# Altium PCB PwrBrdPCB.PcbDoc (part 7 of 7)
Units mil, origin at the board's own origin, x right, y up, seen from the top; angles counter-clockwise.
Board outline 8000 x 5500 mil, 4 copper layers (Top Layer, Internal 1, Internal 2, Bottom Layer), stack 61.834 mil thick; 682 components, 380 nets, 1899 pads, 766 vias.
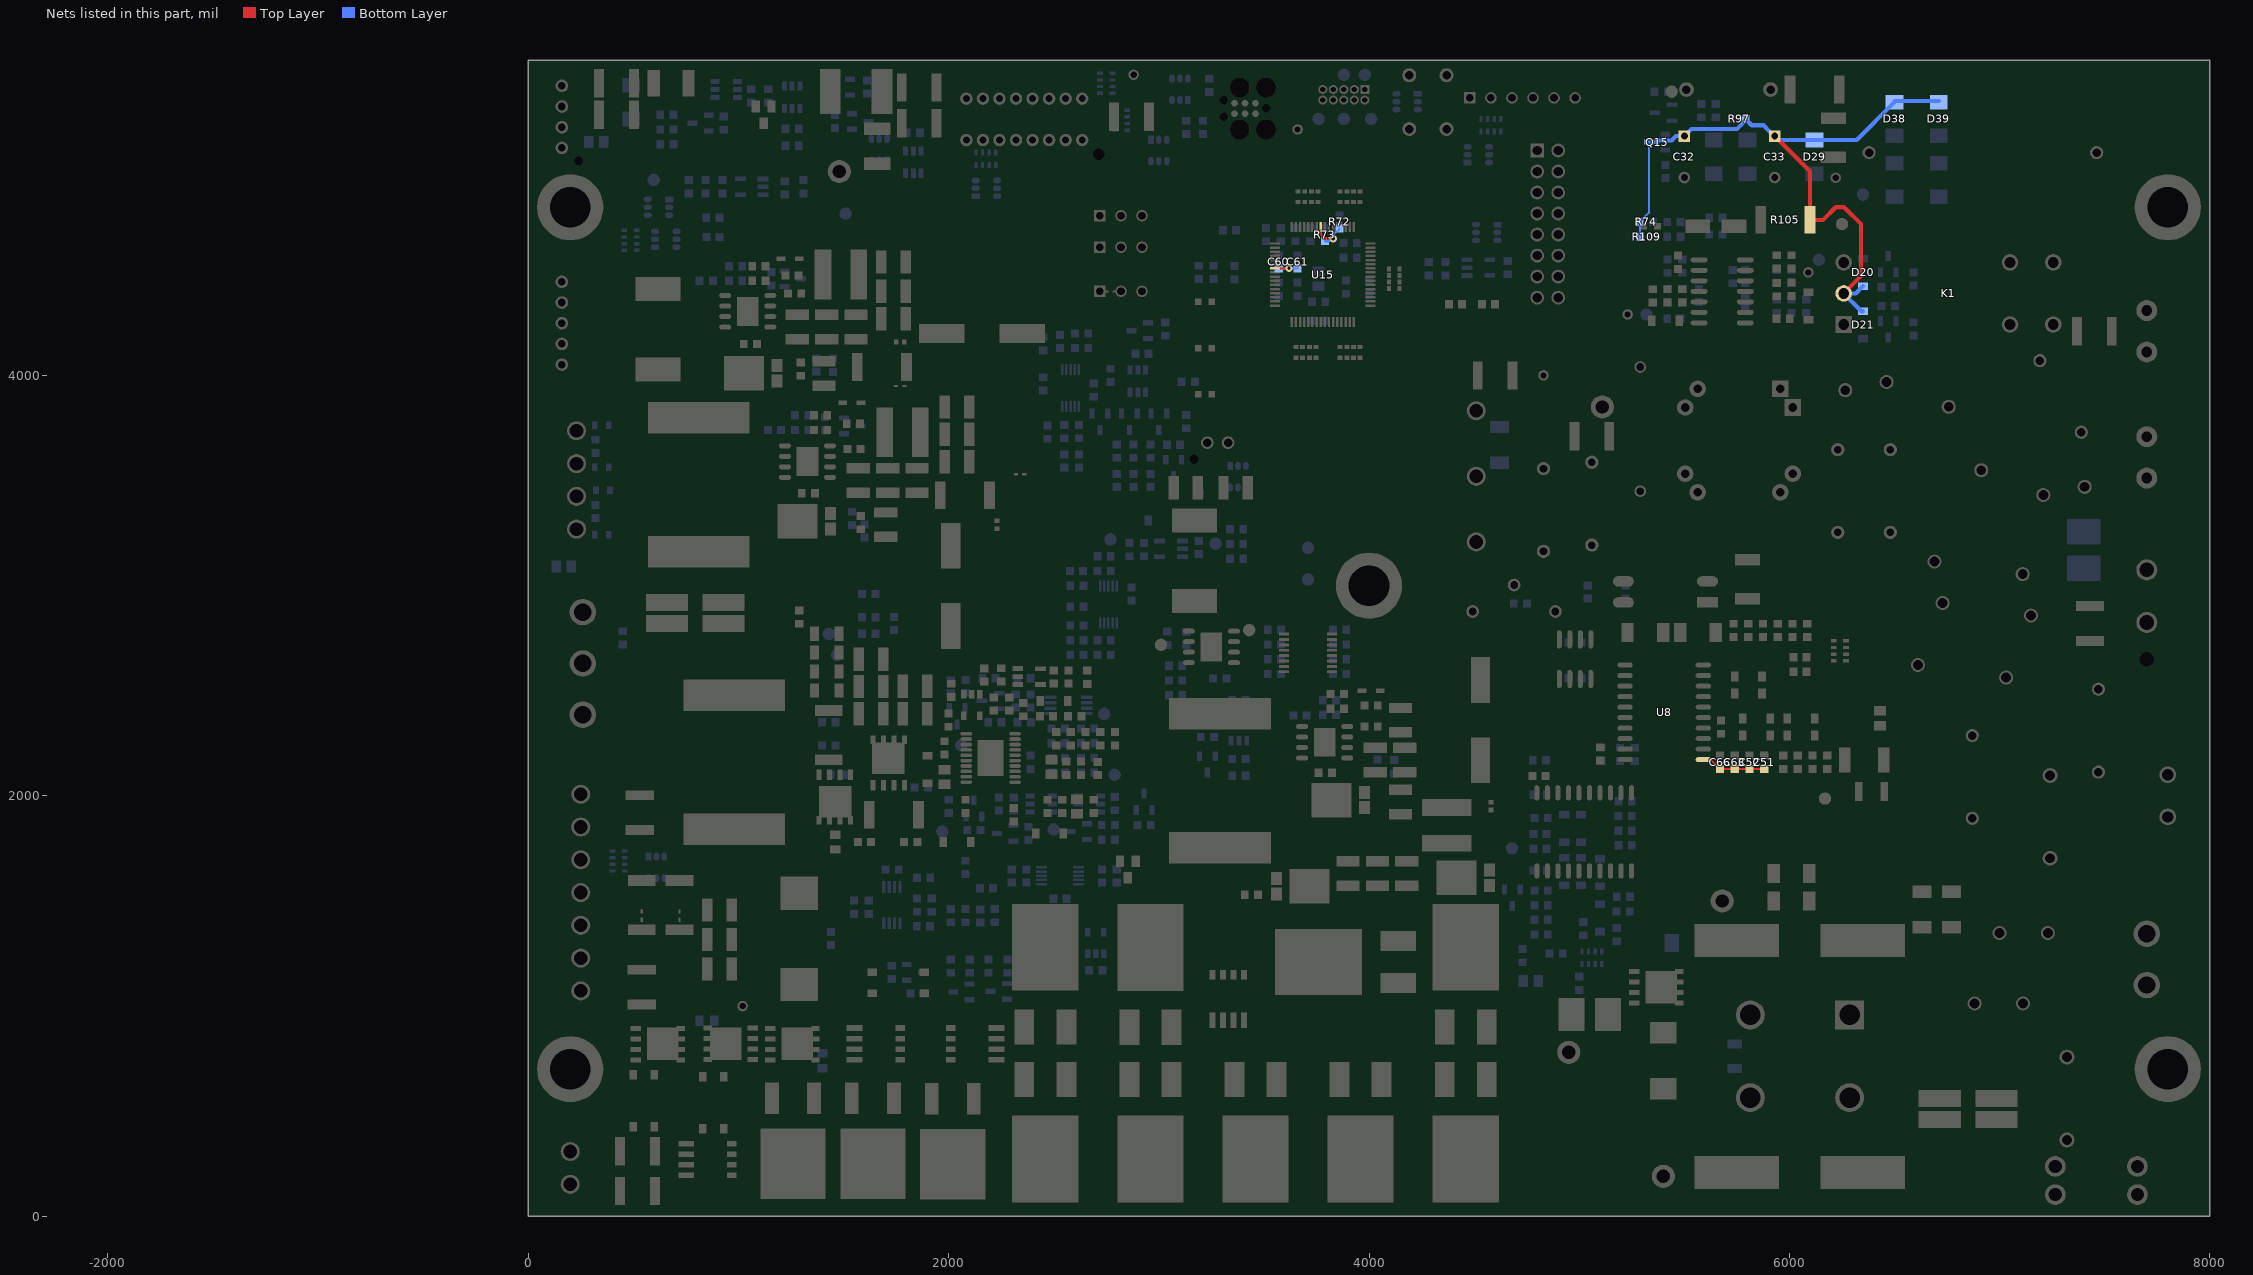
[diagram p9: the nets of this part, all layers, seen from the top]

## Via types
v1: diameter 35, hole 16, Top Layer to Bottom Layer, tented both sides, 409 vias
v2: diameter 35, hole 16, Top Layer to Bottom Layer, 348 vias
v3: diameter 35, hole 16, Top Layer to Bottom Layer, tented bottom, 5 vias
v4: diameter 60, hole 36, Top Layer to Bottom Layer, 2 vias
v5: diameter 65, hole 40.5, Top Layer to Bottom Layer, 2 vias

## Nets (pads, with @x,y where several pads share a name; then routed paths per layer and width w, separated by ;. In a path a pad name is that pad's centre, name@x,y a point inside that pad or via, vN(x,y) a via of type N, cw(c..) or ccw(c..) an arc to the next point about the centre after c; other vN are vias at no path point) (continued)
Vcoil: C32.+ C33.+ D20.K D21.K D29.K D38.K D39.K K1.PLUS Q15.3 R74.2 R97.2 R105.1 R109.2 | length 3385.7
  Top Layer w20: C33.+@5930,5138.43 6097.13,4971.3 R105.1@6097.13,4740 6160,4740 6220,4800 6260,4800 6340,4720 6340,4472.29 K1.PLUS@6257.71,4390
  Bottom Layer w10: R109.2@5288.5,4660 5288.5,4728.5 R74.2@5287.01,4730 5331,4773.99 Q15.3@5331,5110
  Bottom Layer w20: Q15.3@5331,5110 5370,5110 5377.9,5117.9 5439.66,5117.9 5460.19,5138.43 C32.+@5500,5138.43 5533.57,5172 5750.46,5172 5791.5,5213.04 R97.2@5791.5,5219.02 ; R97.2@5791.5,5220 R97.2@5791.5,5219.02 ; D21.K@6350,4305.35 6342.36,4305.35 K1.PLUS@6257.71,4390 6315.36,4390 D20.K@6350,4424.65 ; D39.K@6710,5305 6500,5305 D38.K@6500,5300 6320,5120 D29.K@6120,5120 5948.43,5120 C33.+@5930,5138.43 5928.23,5138.43 5928.23,5140.2 5912.44,5155.98 5910.67,5155.98 5876.65,5190 5820.51,5190 R97.2@5791.5,5219.02
VCORE: C60.1 C61.1 U15.55 | length 156.8
  Top Layer w10: U15.55@3553.62,4509.53 v1(3619.53,4509.53)
  Bottom Layer w10: C60.1@3570,4508.5 3571.02,4509.53 v1(3619.53,4509.53) 3658.98,4509.53 C61.1@3660,4508.5
VDDMON: C51.1 C52.1 C63.1 C66.1 U8.1 | length 308
  Top Layer w10: U8.1@5590.12,2172.24 5626.26,2172.24 C66.1@5670,2128.5 C63.1@5740,2128.5 C52.1@5810,2128.5 C51.1@5880,2128.5
WAKE_INT: R72.1 R73.2 U15.41 | length 210.3
  Top Layer w10: U15.41@3770.16,4706.38 3770.16,4669.84 3790,4650 v1(3830,4650)
  Bottom Layer w10: R73.2@3790,4638.5 3808.5,4638.5 3820,4650 v1(3830,4650) 3830,4668.5 R72.1@3860,4698.5
pads on no net: D10.3 D30.4 JP4.0 JP7.0 JP7.2 JP9. JP10.0 JP10.6 JP11.6 JP11.7 JP11.8 JP12.2 JP12.3 JP12.6 JP14.3 JY1.1 JY2.1 JY5.0 LA4.4 LA4.5 LA5.1 LA5.8 LA6.4 LA6.5 LA7.4 LA7.5 U3.1 U3.4 U4.14 U6.3 U8.12 U8.14 U13.2 U14.2 U18.4 U26.2 U29.3 Z1.1 Z5.1 Z6.1 Z9.1
copper on no net: | length 9736
  Top Layer w8: -2122,4675 -1000,4675 -1000,4770 -2122,4770 -2122,4675
  Internal 1 w8: -2122,4556 -1000,4556 -1000,4651 -2122,4651 -2122,4556
  Internal 2 w8: -2122,4439 -1000,4439 -1000,4534 -2122,4534 -2122,4439
  Bottom Layer w8: -2122,4321 -1000,4321 -1000,4416 -2122,4416 -2122,4321

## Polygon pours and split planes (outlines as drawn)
GND_AUX2 on Top Layer "aux2gnd-top" (solid, remove dead copper, pour order 72): 240,4520 870,4520 900,4550 1290,4550 1350,4610 1840,4610 1880,4570 1880,4350 2300,4350 2430,4220 2430,3950 2030,3950 2030,4030 1600,4030 1600,3900 240,3900
GND_ISO on Top Layer "gndisolarge-top" (solid, remove dead copper, pour order 76): 500,4530 500,5460 1870,5460 1870,5020 1890,5000 2780,5000 2880,5100 2880,5460 5040,5460 5040,4320 4210,4320 4210,3400 4510,3100 5280,3100 5310,3070 5310,1530 4520,1530 3350,2700 3350,3350 3310,3390 2460,3390 2460,4230 2310,4380 1910,4380 1910,4560 1830,4640 1330,4640 1270,4580 880,4580 830,4530
DCBUS on Top Layer "dcbus-top" (solid, remove dead copper, pour order 30): 715,291.81 650,340 650,370.55 650,1210 950,1510 1170,1510 1170,1430 1424.09,1430 1605.45,1620 2210,1620 2210,980 1070,980 1010,920 1010,400 880,400 880,291.81
GND_AUX1 on Top Layer "aux1gnd-top" (solid, remove dead copper, pour order 70): 360,3880 2150,3880 2150,3480 1990,3447.33 1990,3412 2150,3380 2150,2670 1900,2670 1820,2750 1820,3070 360,3070
PVPROT on Top Layer "pvprot-top" (solid, remove dead copper, pour order 8): 5990,30 5990,690 4660,690 4660,1458.06 3340,1450 3340,1630 2230,1630 2230,680 1110,680 1110,25
12V_ISO on Top Layer "12-top" (solid, remove dead copper, pour order 74): 3600,1680 2790,1680 2790,2300 2170,2920 2170,3220 2980,3220 2980,2280 3110,2150 3350,2150 3600,1900
GND_ISO on Top Layer "gndisosmall-top" (solid, remove dead copper, pour order 28): 4690,720 5020,720 5020,1050 4690,1050
N2 on Top Layer "n2-top" (solid, remove dead copper, pour order 40): 5050,3840 5050,3400 5640,3400 5630,3410 5630,3700 5310,3700 5170,3840
L2 on Top Layer "l2-top" (solid, remove dead copper, pour order 38): 5630,3800 5630,4070 4660,4070 4660,3930 5230,3930 5360,3800
LPROT on Top Layer "lprot-top" (solid, remove dead copper, pour order 36): 5840,3810 6100,3810 6140,3900 6140,4030 6300,4060 6520,4060 6590,3990 6590,3770 6730,3770 7090,4130 7090,4580 7010,4580 7000,4570 7000,4350 6800,4150 5950,4150 5840,4040
NetFC1_2 on Top Layer "pv-fused" (solid, pour order 0): 7430,30 7430,500 6890,500 6890,30
POS1 on Top Layer "pv-pos1" (solid, pour order 2): 6810,25 6810,490 6550,490 6350,690 6100,690 6100,25
PVNEG on Top Layer "pvneg-top" (solid, pour order 4): 6890,520 6890,1480 7830,1480 7830,1260 7620,1260 7170,810 7180,800 7180,520
NEG1 on Top Layer "pvneg1-top" (solid, pour order 6): 6810,520 6810,1250 6740,1250 6670,1320 6670,1400 6100,1400 6100,830 6310,830 6620,520
NEG2 on Top Layer "pvneg2-top" (solid, pour order 10): 5990,830 5990,1530 5950,1570 5460,1570 5390,1500 5390,920 5340,830
DCMON.N3 on Top Layer "dcmonn3-top" (solid, pour order 12): 5110,1360 5280,1360 5290,1350 5290,880 5110,880
HVX_SW on Top Layer "hvxsw-top" (solid, pour order 14): 740,1800 1650,1800 1650,1980 1670,2000 1740,2000 1750,2010 1750,2080 1590,2080 1550,2040 740,2040
GND_AUX3 on Internal 1 "gndaux3-gnds" (solid, remove dead copper, pour order 16): 2690,1770 2750,1830 2750,2310 2470,2590 1910,2590 1760,2740 1760,3030 890,3030 890,2650 850,2610 730,2610 730,1470 1420,1470 1710,1770
GND_ISO on Internal 1 "gndiso-gnds" (solid, remove dead copper, pour order 44): 4690,720 5310,720 5310,3070 5280,3100 4510,3100 4210,3400 4210,4320 4960,4320 5040,4400 5040,4980 5040,5040 5040,5500 -10,5500 -10,4750 500,4750 500,4540 510,4530 830,4530 880,4580 1270,4580 1330,4640 1830,4640 1910,4560 1910,4380 2310,4380 2500,4190 2500,4140 2460,4100 2460,3050 3110,2390 3110,1720 2860,1480 1860,1480 1410,1010 2800,1000 2950,1150 3230,1450 4690,1450
GND_ISO on Internal 1 "gndiso_trace" (solid, remove dead copper, pour order 66): 440,1010 1350,1010 1850,1510 2290,1510 2290,1520 2340,1570 2440,1570 2500,1510 2850,1510 2940,1600 2940,1620 2960,1640 2990,1640 3090,1740 3090,2380 2440,3030 2440,4120 2410,4150 1830,4150 1800,4120 1800,3930 1830,3900 2150,3900 2170,3880 2170,2660 2220,2610 2490,2610 2770,2330 2770,1780 2740,1750 1730,1750 1420,1440 440,1440
GND_AUX1 on Internal 1 "gndaux1-gnds" (solid, remove dead copper, pour order 20): 360,3070 1820,3070 1820,2750 1900,2670 2150,2670 2150,3870 2140,3880 360,3880
GND_MON on Internal 1 "gndmon-gnds" (solid, remove dead copper, pour order 48): 5540,1940 5540,2860 6300,2860 6300,1940
GND_PROT on Internal 1 "gndprot-gnds" (solid, remove dead copper, pour order 60): 5320,5390 5320,4240 6640,4240 6640,5390
GND_AUX2 on Internal 1 "gndaux2-gnds" (solid, remove dead copper, pour order 22): 400,3940 1710,3940 1710,4160 1720,4170 2460,4170 2460,4190 2300,4350 1880,4350 1880,4570 1840,4610 1350,4610 1290,4550 900,4550 830,4480 400,4480
3V3_ISO on Internal 2 "3v3iso-pwrs" (solid, remove dead copper, pour order 46): 5310,1450 5310,3070 5280,3100 4510,3100 4210,3400 4210,4320 4960,4320 5040,4400 5040,4980 5040,5100 5040,5500 0,5500 0,4750 500,4750 500,4530 830,4530 880,4580 1270,4580 1330,4640 1830,4640 1910,4560 1910,4380 2310,4380 2500,4190 2500,4140 2430,4070 2430,3070 3110,2390 3110,1720 2870,1490 1860,1480 1720,1330 1723.94,1003.94 2240,1003.94 2240,1450 3090,1450
DCBUS on Internal 2 "dcbus_trace" (solid, remove dead copper, pour order 68): 1040,760 1040,950 1070,980 1630,980 1690,1040 1690,1350 1850,1510 2280,1510 2340,1570 2440,1570 2500,1510 2850,1510 3090,1750 3090,2380 2640,2830 2410,2830 2100,3140 2100,4040 1870,4270 1870,4550 1820,4600 1460,4600 1410,4550 1410,4040 1770,3680 1770,2750 1900,2620 2500,2620 2780,2340 2780,1810 2720,1750 1750,1750 1240,1240 750,1240 750,760
VCC_AUX3 on Internal 2 "vccaux3-pwrs" (solid, remove dead copper, pour order 18): 1880,1770 1880,2170 1990,2280 1990,2590 2470,2590 2750,2310 2750,1830 2690,1770
GND_ISO on Internal 2 "gndisoforcomp-pwrs" (solid, remove dead copper, pour order 26): 450,1210 720,1210 720,1800 710,2200 710,2540 850,2650 1390,2640 1390,2770 1730,2920 1730,3000 1730,3090 850,3090 780,3030 780,2780 570,2600 570,2240 450,2240 450,2110 450,1930
Vcc_prot on Internal 2 "vccprot-pwrs" (solid, remove dead copper, pour order 62): 5320,5390 5320,4240 6640,4240 6640,5390
GND_ISO on Bottom Layer "gndisoCPU-bot" (solid, remove dead copper, pour order 50): 4690,1030 5310,1030 5310,1940 6300,1940 6300,2860 5310,2860 5310,3070 5270,3110 4500,3110 4210,3400 4210,4320 4870,4980 5160,4980 5160,5500 0,5500 0,4750 500,4750 500,4530 820,4530 870,4580 1270,4580 1330,4640 1830,4640 1910,4560 1910,4380 2320,4380 2500,4200 2500,4140 2450,4090 2440,4090 2440,3020 3090,2370 3090,1453 3087,1450 4690,1450
GND_AUX2 on Bottom Layer "gndaux2-bot" (solid, remove dead copper, pour order 56): 400,3940 1700,3940 1730,3970 2420,3970 2420,4230 2300,4350 2100,4350 1840,4610 1350,4610 1290,4550 890,4550 840,4500 400,4500
NEG2 on Bottom Layer "neg2-bot" (solid, remove dead copper, pour order 58): 5350,830 5980,830 5990,840 5990,1210 5350,1210
GND_AUX3 on Bottom Layer "gndaux3-bot" (solid, remove dead copper, pour order 52): 1310,2770 1810,2770 1990,2590 2490,2590 2730,2350 2730,1810 2690,1770 1840,1770 1840,2090 1310,2090
GND_AUX1 on Bottom Layer "gndaux1-bot" (solid, remove dead copper, pour order 54): 460,3070 2150,3070 2160,3080 2160,3880 460,3880
GND_ISO on Bottom Layer "gndiso-bot" (solid, remove dead copper, pour order 24): 5020,1010 5020,40 580,50 580,340 420,500 420,1320 490,1390 750,1390 790,1350 790,1100 1000,890 2820,890 3240,1310 3500,1310 3800,1010
PVNEG on Bottom Layer "pvneg-bot" (solid, remove dead copper, pour order 64): 6890,530 7180,530 7180,820 7620,1260 7830,1260 7830,1480 6890,1480
GND on Bottom Layer "earth-bot" (solid, remove dead copper, pour order 42): 8000,2200 8010,2190 8010,1770 6680,1770 6560,1890 6560,2080 6680,2200
PROT.NPROT on Bottom Layer "nprot-bot" (solid, remove dead copper, pour order 34): 7480,3310 7410,3310 7240,3480 6820,3480 6700,3600 6420,3600 6290,3730 6220,3660 5930,3660 5840,3570 5840,3380 5870,3350 6590,3350 6780,3160 6850,3160 7010,3320 7270,3320
HVX_DCBUS on Bottom Layer "hvxdcbus-bot" (solid, remove dead copper, pour order 32): 1600,1570 1770,1740 1810,1740 1810,2070 1190,2070 1190,1570

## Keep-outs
Keep-Out Layer:
  circle w10: c7800,4800 r170
  circle w10: c200,4800 r170
  circle w10: c200,700 r170
  circle w10: c4000,3000 r170
  lines w10: 25,4170 25,4420 ; 25,25 1512.5,25 3025,25 7975,25 7975,5475 25,5475 25,25

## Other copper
Top Layer:
  rectangle net NetF5_2: 502.87,5330.74 597.32,5449.84
  rectangle net FAN_DRAIN: 762.68,5330.74 868.31,5449.84
  rectangle net NetD57_1: 1154.32,5279.37 1436.97,5449.84
  rectangle net NetD57_1: 1157.4,5279.37 1436.97,5284.98
  rectangle net GND_ISO: 2210,3360 2390,3500
  rectangle net NetQ32_S: 1420,2080 1550,2210
  rectangle: -2122,4675 -1932,4770
  region net HVX_DCBUS: 1200,1460 1200,1730 1310,1730 1340,1760 1520,1760 1520,1560 1420,1460
  region net GND_AUX3: 1150,1550 1150,1730 744.7,1730 744.7,1550 870,1490 930,1550
  pour cut-out: 1920,5500 1920,5000 2760,5000 2760,5500
  region net HVX_DCBUS: 1640,2110 1640,2310 1670,2340 1670,2700 1730,2700 1820,2610 1820,2140 1790,2110
  region net GND_AUX3: 1440,2340 1440,2810 1370,2870 1070,2870 1050,2880 830,2880 830,3040 1750,3040 1750,2740 1620,2740 1620,2340
  region net NetC153_1: 150,2280 590,2280 660,2350 660,2610 740,2690 750,2730 760,2780 760,2860 550,2860 420,2730 420,2610 330,2520 150,2520
  region net NetC153_2: 760,2880 520,2880 370,2730 150,2730 150,3040 710,3040 760,2960
  region net NetC90_2: 1320,3230 1320,3460 1290,3460 1240,3510 1240,3520 1190,3520 1050,3650 1050,3760 610,3760 1160,3230
  region net 12V_AUX1: 370,3090 1630,3090 1750,3210 1750,3260 1630,3260 1610,3280 1550,3280 1550,3250 1490,3190 370,3190
  region net DCBUS: 1900,3610 1950,3560 2010,3560 2010,3900 1830,3900 1830,3840
  region net DCBUS: 1650,4300 1600,4350 1600,4600 1700,4600 1700,4300
  region net GND_AUX2: 1160,4150 1210,4200 1600,4200 1600,4060 1590,4050 1220,4050 1210,4040 1210,3990 1160,3990
  region net NetC98_2: 1040,3980 1040,4170 1010,4170 940,4240 890,4240 719.05,4410.95 509.06,4410.94 940,3980
  region net NetC17_2: 3780,2120 3740,2120 3690,2170 3690,2190 3640,2190 3510,2320 3280,2320 3690,1900 3780,1900
  region net GND_ISO: 3950,1920 4000,1920 4000,1960 4040,2000 4200,2000 4200,2140 3950,2140
  region net NetC24_1: 4030,2210 4200,2210 4270,2150 4270,1980 4450,1980 4450,2210 4340,2320 4100,2320 4110,2310 4110,2250 4030,2250
  region net HVX_VOUT: 1270,2400 1340,2470 1390,2470 1390,2800 1360,2830 830,2830 830,2680 740,2590 740,2400
  region net PV_SEL-: 1040,870 1100,870 1110,880 1130,900 1180,900 1180,770 1120,770 1110,760 1090,740 1040,740
  text "TOP LAYER *.GTL" at -1862,4702 h40
Internal 1:
  rectangle: -2122,4557 -1932,4652
  pour cut-out: 1920,5460 1920,5020 2760,5020 2760,5460
  text "INTERNAL LAYER 1 *.G1" at -1862,4584 h40
Internal 2:
  rectangle: -2122,4439 -1932,4534
  pour cut-out: 1910,5470 1910,5040 2760,5040 2760,5470
  text "INTERNAL LAYER 2 *.G2" at -1862,4466 h40
Bottom Layer:
  rectangle net NetFC1_2: 6890,40 7430,490
  rectangle net PVPROT: 5060,40 5990,690
  rectangle net NetL9_1: 3200,2650 3300,2770
  rectangle net PVPROT: 2380,1080 2590,1410
  rectangle net DCBUS: 880,760 1000,880
  rectangle net PVPROT: 1070,760 1760,910
  rectangle: -2122,4321 -1932,4416
  region net GND_AUX1: 1820,2990 1820,2790 1920,2690 2380,2690 2420,2730 2420,2990
  region net NEG1: 6100,830 6310,830 6610,530 6700,530 6700,1290 6590,1400 6100,1400
  region net POS1: 6100,40 6100,690 6350,690 6550,490 6810,490 6810,40
  region net DCBUS: 870,1160 870,936 870,760 1050,760 1050,970 1660,970 1660,1160
  region net GND_AUX3: 730,1730 730,1570 950,1350 1150,1350 1150,1730
  region net PVPROT: 3830,1040 3510,1360 3510,1420 4640,1420 4640,1040
  region net PVPROT: 2820,1460 3040,1460 3040,1340 2820,1120
  region net HVX_VOUT: 890,2950 890,2700 730,2540 730,1770 1150,1770 1150,2110 1280,2110 1280,2410 1280,2980 920,2980
  pour cut-out: 1920,5000 2760,5000 2760,5500 1920,5500
  text "BOTTOM LAYER *.GBL" at -1862,4348 h40

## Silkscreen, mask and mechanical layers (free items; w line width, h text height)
Top Overlay:
  drawing of 178 lines, arcs and shapes, not listed
  text "FTDI cable" at 4530,5400 h50
  text "Fan+" at 840,5390 h60
  text "BLK" at 4450,5250 h60 r270
  text "BRN" at 4550,5250 h60 r270
  text "RED" at 4650,5250 h60 r270
  text "OR" at 4750,5250 h60 r270
  text "YEL" at 4850,5250 h60 r270
  text "GRN" at 4950,5250 h60 r270
  text "Fan-" at 580,5231.89 h60
  text "reset" at 4140,5080 h60
  text "1" at 2760,5050 h60
  text "5V" at 5060,5050 h60
  text "FG" at 370,5020 h60
  text "GND" at 4470,5010 h60
  text "TP15" at 2002.58,4990 h40 r270
  text "Comp" at 2082.58,4990 h40 r270
  text "FG" at 2162.58,4990 h40 r270
  text "Fan" at 2242.58,4990 h40 r270
  text "12V" at 2322.58,4990 h40 r270
  text "GND" at 2402.58,4990 h40 r270
  text "PComp" at 2482.58,4990 h40 r270
  text "AC OK" at 2562.58,4990 h40 r270
  text "1" at 330,4970 h50
  text "12V" at 4980,4960 h60
  text "TOP OVERLAY *.GTO" at -1862,4938 h40
  text "3V3" at 4470,4930 h60
  text "AC over / voltage" at 5050,4910 h60 r270
  text "GND ISO" at 1030,4860 h60
  text "SDA" at 4470,4830 h60
  text "normal / prog" at 3020,4810 h60
  text "PWR_WAKE" at 2002.58,4770 h40 r270
  text "SEL/test" at 2082.58,4770 h40 r270
  text "nRST" at 2162.58,4770 h40 r270
  text "Bat+" at 2242.58,4770 h40 r270
  text "5V" at 2322.58,4770 h40 r270
  text "PWR2DAQ" at 2402.58,4770 h40 r270
  text "DAQ2PWR" at 2482.58,4770 h40 r270
  text "GND" at 2562.58,4770 h40 r270
  text "SCL" at 4470,4740 h60
  text "LED0" at 4480,4640 h60
  text "LED1" at 4480,4540 h60
  text "CTL_COMP" at 4270,4450 h60
  text "spare" at 4290,4380 h60
  text "LED1" at 3310,4330 h60
  text "PWR | CTL" at 2610,4250 h50
  text "RED" at 3310,4250 h60
  text "2A fuse" at 7830,4130 h60 r270
  text "LED0" at 3310,4120 h60
  text "COMP.EN / source" at 2650,4100 h50
  text "YEL" at 3310,4050 h60
  text "1" at 310,3950 h60
  text "power" at 3310,3890 h60
  text "Revision" at 3640,3880 h60
  text "GND" at 3090,3780 h60
  text "5V" at 3300,3780 h60
  text ".nhRev" at 3685,3680 h120
  text "+5" at 25,3630 h60 r270
  text "NH-GG MF / Solar Power / Board" at 2370,3610 h60
  text "Serial #" at 3630,3550 h60
  text "c 2020-03" at 2400,3500 h60
  text "+12" at 30,3340 h60 r270
  text "Licensed under" at 2288.8,3190 h50
  text "1" at 290,3130 h60
  text "CERN-OHL-P v2" at 2288.8,3120 h50
  text "Source package at" at 2288.8,3050 h50
  text "AC / Line" at 7310,3030 h60
  text "Neg" at 40,3020 h60 r270
  text "docs.2to8.cc" at 2288.8,2980 h50
  text "5V" at 3470,2860 h60
  text "12V" at 2820,2750 h60
  text "CR2032" at 4540,2710 h50
  text "AC / Neut" at 7330,2540 h60
  text "Pos" at 50,2400 h60 r270
  text "1" at 510,2310 h60
  text "EARTH" at 7624.72,2124.72 h60 r270
  text "-" at 60,1970 h60
  text "C" at 60,1820 h60
  text "+" at 60,1670 h60
  text "D" at 60,1510 h60
  text "PV-" at 7340,1410 h60 r270
  text "trt" at 40,1350 h60
  text "T" at 60,1200 h60
  text "PV+" at 7340,1150 h60 r270
  text "ts" at 40,1070 h60
  text "1" at 80,960 h60
  text "PV-" at 5030,730 h60
  text "EARTH" at 7655.28,434.72 h60
  text "Pos" at 50,390 h60
  text "PV+" at 5350,280 h60
  text "20A fuse" at 6670,180 h60
  text "1" at 80,140 h60
  text "Neg" at 40,50 h60
Bottom Overlay:
  drawing of 151 lines, arcs and shapes, not listed
  text "BOTTOM OVERLAY *.GBO" at -1862,3994 h40
  text "Licensed under" at 3871.35,878.04 h50
  text "CERN-OHL-P v2" at 3871.35,799.3 h50
  text "Source package at" at 3871.35,720.56 h50
  text "https://docs.2to8.cc" at 3871.35,641.82 h50
Top Paste:
  rectangle: -2122,5029 -1932,5124
  lines w8: -2122,5029 -2122,5124 -1000,5124 -1000,5029 -2122,5029
  text "TOP PASTE *.GTP" at -1862,5056 h40
Bottom Paste:
  rectangle: -2122,4085 -1932,4180
  lines w8: -2122,4085 -1000,4085 -1000,4180 -2122,4180 -2122,4085
  text "BOTTOM PASTE *.GBP" at -1862,4112 h40
Top Solder:
  rectangle: -2122,4793 -1932,4888
  lines w8: -2122,4793 -1000,4793 -1000,4888 -2122,4888 -2122,4793
  text "TOP SOLDER MASK *.GTS" at -1862,4820 h40
Bottom Solder:
  rectangle: 850,310 4930,560
  rectangle: 3740,2190 3840,2320
  rectangle: 3200,2650 3290,2770
  rectangle: 2140,2100 2260,2260
  rectangle: 1280,3520 1380,3660
  rectangle: 1000,4240 1090,4370
  rectangle: 1070,2670 1230,2810
  rectangle: 1640,2110 1780,2250
  rectangle: 5360,1020 5450,1160
  rectangle: 890,770 990,870
  rectangle: 1230,770 1330,870
  rectangle: -2122,4203 -1932,4298
  lines w8: -2122,4203 -1000,4203 -1000,4298 -2122,4298 -2122,4203
  lines w30: 810,220 860,220 ; 810,320 860,320 ; 1170,120 4610,120
  text "BOTTOM SOLDER MASK *.GBS" at -1862,4230 h40
1 Fab Drawing:
  circle w10: c200,4800 r75
  circle w10: c200,700 r75
  circle w10: c7800,700 r75
  circle w10: c7800,4800 r75
  circle w10: c4000,3000 r75
  lines w5: -6580,-3400 9120,-3400 9120,7600 -6580,7600 -6580,-3400
  lines w10: 4618.38,-3031.5 8868.38,-3031.5 ; 4618.38,-2531.5 8868.38,-2531.5 ; 4618.38,-2031.5 8868.38,-2031.5
  text "NEW HORIZONS, GHL" at 4723.38,-2401.5 h250
  text "PROJECT" at 4711.1,-2631.5 h60
  text "REV" at 7416.02,-2631.5 h60
  text "'.nhRev'" at 7386.02,-2906.5 h280
  text "'.nhProjName'" at 4740.98,-2915.2 h260
  text "FABRICATION DRAWING" at 6193.38,-3186.5 h100
2 Board Outline:
  rectangle: -2122,3849 -1932,3944
  lines w8: -2122,3849 -2122,3944 -1000,3944 -1000,3849 -2122,3849
  lines w10: 0,0 2500,0 3000,0 8000,0 8000,5500 0,5500 0,0
  lines w93: 7600,2950 7800,2950
  text "BOARD OUTLINE *.GM2" at -1862,3876 h40
4 Gerber All:
  lines w8: -2222,3767.67 -2222,5434 -900,5434 -900,3767.67 -2222,3767.67
  lines w10: -1932,5214 -1162,5214
  text "LAYER USAGE" at -1932,5242 h80
5 Assembly Top:
  lines w5: -6580,-3400 -6580,7600 9120,7600 9120,-3400 -6580,-3400
  lines w10: 4618.38,-3031.5 8868.38,-3031.5 ; 4618.38,-2531.5 8868.38,-2531.5 ; 4618.38,-2031.5 8868.38,-2031.5
  text "NEW HORIZONS, GHL" at 4723.38,-2401.5 h250
  text "PROJECT" at 4711.1,-2631.5 h60
  text "REV" at 7416.02,-2631.5 h60
  text "PRIMARY SIDE" at -727.76,-2706.54 h300
  text "'.nhRev'" at 7386.02,-2906.5 h280
  text "'.nhProjName'" at 4740.98,-2915.2 h260
  text "ASSEMBLY DRAWING, TOP" at 6193.38,-3186.5 h100
6 Assembly Bot:
  lines w5: -6580,-3400 -6580,7600 9120,7600 9120,-3400 -6580,-3400
  lines w10: -6428.39,-3031.5 -2178.39,-3031.5 ; -6428.39,-2531.5 -2178.39,-2531.5 ; -6428.39,-2031.5 -2178.39,-2031.5
  text "NEW HORIZONS, GHL" at -2283.39,-2401.5 h250
  text "REV" at -4976.03,-2631.5 h60
  text "Project" at -2271.11,-2631.5 h60
  text "SECONDARY SIDE" at 3082.24,-2701.54 h300
  text "'.nhRev'" at -4946.03,-2906.5 h280
  text "'.nhProjName'" at -2300.99,-2915.2 h260
  text "ASSEMBLY DRAWING, BOTTOM" at -3753.39,-3186.5 h100
7 Fab Notes:
  drawing of 304 lines, arcs and shapes, not listed
  text "MATERIAL:  FR4" at -6067.8,7357.29 h100
  text "4 LAYERS OF 1OZ COPPER" at -6067.8,7257.29 h100
  text "SILVER IMMERSION" at -6067.8,7157.29 h100
  text "FINISHED BOARD THICKNESS = 0.062\" / 1.57mm" at -6067.8,6957.29 h100
  text "UL 94V-0" at -6067.8,6857.29 h100
  text "GREEN SOLDERMASK OVER BARE COPPER, BOTH SIDES" at -6067.8,6657.29 h100
  text "WHITE SILKSCREEN OVER SOLDERMASK" at -6067.8,6557.29 h100
  text "DIMENSIONS IN MILS (0.001\")" at -6067.8,6357.29 h100
  text "dia 0.200in (5mm) x5" at 400,5700 h60
  text "Layer" at -5922.5,1957.5 h60
  text "Name" at -5512.59,1957.5 h60
  text "Material" at -4582.84,1957.5 h60
  text "Thickness" at -3723.08,1957.5 h60
  text "Constant" at -3073.24,1957.5 h60
  text "Board Layer Stack" at -2503.38,1957.5 h60
  text "Top Overlay" at -5512.59,1837.5 h60
  text "Top Solder" at -5512.59,1717.5 h60
  text "Solder Resist" at -4582.84,1717.5 h60
  text "0.40mil" at -3723.08,1717.5 h60
  text "3.5" at -3073.24,1717.5 h60
  text "1" at -5922.5,1597.5 h60
  text "Top Layer" at -5512.59,1597.5 h60
  text "1.40mil" at -3723.08,1597.5 h60
  text "Dielectric 1" at -5512.59,1477.5 h60
  text "FR-4" at -4582.84,1477.5 h60
  text "14.10mil" at -3723.08,1477.5 h60
  text "4.2" at -3073.24,1477.5 h60
  text "2" at -5922.5,1357.5 h60
  text "Internal 1" at -5512.59,1357.5 h60
  text "1.42mil" at -3723.08,1357.5 h60
  text "Dielectric 3" at -5512.59,1237.5 h60
  text "FR-4" at -4582.84,1237.5 h60
  text "28.00mil" at -3723.08,1237.5 h60
  text "4.2" at -3073.24,1237.5 h60
  text "3" at -5922.5,1117.5 h60
  text "Internal 2" at -5512.59,1117.5 h60
  text "1.42mil" at -3723.08,1117.5 h60
  text "Dielectric 2" at -5512.59,997.5 h60
  text "FR-4" at -4582.84,997.5 h60
  text "14.10mil" at -3723.08,997.5 h60
  text "4.2" at -3073.24,997.5 h60
  text "4" at -5922.5,877.5 h60
  text "Bottom Layer" at -5512.59,877.5 h60
  text "1.40mil" at -3723.08,877.5 h60
  text "Bottom Solder" at -5512.59,757.5 h60
  text "Solder Resist" at -4582.84,757.5 h60
  text "0.40mil" at -3723.08,757.5 h60
  text "3.5" at -3073.24,757.5 h60
  text "Bottom Overlay" at -5512.59,637.5 h60
  text "NEW HORIZONS, GHL" at 4723.38,-2401.5 h250
  text "PROJECT" at 4711.1,-2631.5 h60
  text "REV" at 7416.02,-2631.5 h60
  text "'.nhEngName'" at 8105,-2650 h90
  text "'.nhEngPhone'" at 8105,-2750 h90
  text "'.nhEngEmail'" at 8105,-2850 h90
  text "'.nhRev'" at 7386.02,-2906.5 h280
  text "'.nhProjName'" at 4740.98,-2915.2 h260
  text "'.nhToday'" at 8105,-2950 h90
  text "FABRICATION NOTES" at 6191.77,-3186.5 h100
Drill Drawing:
  circle w10: c-5899.38,5035.83 r20
  circle w10: c-5899.38,5035.83 r33.33
  circle w10: c-5899.38,2785.83 r33.33
  lines w10: -5932.71,2619.17 -5916.04,2619.17 -5899.38,2602.5 -5882.71,2619.17 -5866.04,2619.17 -5882.71,2635.83 -5866.04,2652.5 -5882.71,2652.5 -5899.38,2669.17 -5916.04,2652.5 -5932.71,2652.5 -5916.04,2635.83 -5932.71,2619.17 ; -5932.71,2902.5 -5932.71,2919.17 -5916.04,2935.83 -5932.71,2952.5 -5932.71,2969.17 -5916.04,2969.17 -5899.38,2952.5 -5882.71,2969.17 -5866.04,2969.17 -5866.04,2952.5 -5882.71,2935.83 -5866.04,2919.17 -5866.04,2902.5 -5882.71,2902.5 -5899.38,2919.17 -5916.04,2902.5 -5932.71,2902.5 ; -5932.71,3202.5 -5866.04,3202.5 -5866.04,3269.17 -5932.71,3269.17 -5932.71,3202.5 ; -5932.71,3369.17 -5916.04,3369.17 -5899.38,3352.5 -5882.71,3369.17 -5866.04,3369.17 -5882.71,3385.83 -5866.04,3402.5 -5882.71,3402.5 -5899.38,3419.17 -5916.04,3402.5 -5932.71,3402.5 -5916.04,3385.83 -5932.71,3369.17 ; -5932.71,4252.5 -5932.71,4269.17 -5916.04,4285.83 -5932.71,4302.5 -5932.71,4319.17 -5916.04,4319.17 -5899.38,4302.5 -5882.71,4319.17 -5866.04,4319.17 -5866.04,4302.5 -5882.71,4285.83 -5866.04,4269.17 -5866.04,4252.5 -5882.71,4252.5 -5899.38,4269.17 -5916.04,4252.5 -5932.71,4252.5 ; -5932.71,4919.17 -5866.04,4919.17 -5899.38,4852.5 -5932.71,4919.17 ; -5919.38,2915.83 -5919.38,2925.83 -5909.38,2935.83 -5919.38,2945.83 -5919.38,2955.83 -5909.38,2955.83 -5899.38,2945.83 -5889.38,2955.83 -5879.38,2955.83 -5879.38,2945.83 -5889.38,2935.83 -5879.38,2925.83 -5879.38,2915.83 -5889.38,2915.83 -5899.38,2925.83 -5909.38,2915.83 -5919.38,2915.83 ; -5919.38,3215.83 -5879.38,3215.83 -5879.38,3255.83 -5919.38,3255.83 -5919.38,3215.83 ; -5919.38,3375.83 -5909.38,3375.83 -5899.38,3365.83 -5889.38,3375.83 -5879.38,3375.83 -5889.38,3385.83 -5879.38,3395.83 -5889.38,3395.83 -5899.38,3405.83 -5909.38,3395.83 -5919.38,3395.83 -5909.38,3385.83 -5919.38,3375.83
  lines w15: -5992.5,2557.5 -2407.44,2557.5 ; -5992.5,5407.5 -2407.44,5407.5 ; -5441.62,2407.5 -5441.62,5557.5 ; -4841.78,2407.5 -4841.78,5557.5 ; -3692.12,2407.5 -3692.12,5557.5 ; -3186.24,2407.5 -3186.24,5557.5 ; -5992.5,2407.5 -2407.44,2407.5 -2407.44,5557.5 -5992.5,5557.5 -5992.5,2407.5
  text "Symbol" at -5902.5,5452.5 h72
  text "Count" at -5396.62,5452.5 h72
  text "Hole Size" at -4796.78,5452.5 h72
  text "Plated" at -3647.12,5452.5 h72
  text "Hole Type" at -3141.24,5452.5 h72
  text "1" at -5396.62,5302.5 h60
  text "70.00mil (1.778mm)" at -4796.78,5302.5 h60
  text "NPTH" at -3647.12,5302.5 h60
  text "Round" at -3141.24,5302.5 h60
  text "H" at -5931.59,5292.51 h66.67
  text "2" at -5396.62,5152.5 h60
  text "70.00mil (1.778mm)" at -4796.78,5152.5 h60
  text "PTH" at -3647.12,5152.5 h60
  text "Round" at -3141.24,5152.5 h60
  text "I" at -5920.48,5142.51 h66.67
  text "3" at -5396.62,5002.5 h60
  text "40.50mil (1.029mm)" at -4796.78,5002.5 h60
  text "NPTH" at -3647.12,5002.5 h60
  text "Round" at -3141.24,5002.5 h60
  text "3" at -5396.62,4852.5 h60
  text "53.50mil (1.359mm)" at -4796.78,4852.5 h60
  text "PTH" at -3647.12,4852.5 h60
  text "Round" at -3141.24,4852.5 h60
  text "4" at -5396.62,4702.5 h60
  text "93.50mil (2.375mm)" at -4796.78,4702.5 h60
  text "NPTH" at -3647.12,4702.5 h60
  text "Round" at -3141.24,4702.5 h60
  text "V" at -5931.59,4692.51 h66.67
  text "4" at -5396.62,4552.5 h60
  text "98.43mil (2.500mm)" at -4796.78,4552.5 h60
  text "PTH" at -3647.12,4552.5 h60
  text "Round" at -3141.24,4552.5 h60
  text "M" at -5931.59,4542.51 h66.67
  text "5" at -5396.62,4402.5 h60
  text "82.68mil (2.100mm)" at -4796.78,4402.5 h60
  text "PTH" at -3647.12,4402.5 h60
  text "Round" at -3141.24,4402.5 h60
  text "E" at -5931.59,4392.51 h66.67
  text "5" at -5396.62,4252.5 h60
  text "193.00mil (4.902mm)" at -4796.78,4252.5 h60
  text "PTH" at -3647.12,4252.5 h60
  text "Round" at -3141.24,4252.5 h60
  text "7" at -5396.62,4102.5 h60
  text "30.00mil (0.762mm)" at -4796.78,4102.5 h60
  text "PTH" at -3647.12,4102.5 h60
  text "Round" at -3141.24,4102.5 h60
  text "D" at -5931.59,4092.51 h66.67
  text "9" at -5396.62,3952.5 h60
  text "63.00mil (1.600mm)" at -4796.78,3952.5 h60
  text "PTH" at -3647.12,3952.5 h60
  text "Round" at -3141.24,3952.5 h60
  text "J" at -5931.59,3942.51 h66.67
  text "10" at -5396.62,3802.5 h60
  text "25.00mil (0.635mm)" at -4796.78,3802.5 h60
  text "PTH" at -3647.12,3802.5 h60
  text "Round" at -3141.24,3802.5 h60
  text "O" at -5931.59,3792.51 h66.67
  text "11" at -5396.62,3652.5 h60
  text "51.18mil (1.300mm)" at -4796.78,3652.5 h60
  text "PTH" at -3647.12,3652.5 h60
  text "Round" at -3141.24,3652.5 h60
  text "G" at -5931.59,3642.51 h66.67
  text "16" at -5396.62,3502.5 h60
  text "64.96mil (1.650mm)" at -4796.78,3502.5 h60
  text "PTH" at -3647.12,3502.5 h60
  text "Round" at -3141.24,3502.5 h60
  text "C" at -5931.59,3492.51 h66.67
  text "18" at -5396.62,3352.5 h60
  text "43.70mil (1.110mm)" at -4796.78,3352.5 h60
  text "PTH" at -3647.12,3352.5 h60
  text "Round" at -3141.24,3352.5 h60
  text "20" at -5396.62,3202.5 h60
  text "33.00mil (0.838mm)" at -4796.78,3202.5 h60
  text "PTH" at -3647.12,3202.5 h60
  text "Round" at -3141.24,3202.5 h60
  text "20" at -5396.62,3052.5 h60
  text "47.24mil (1.200mm)" at -4796.78,3052.5 h60
  text "PTH" at -3647.12,3052.5 h60
  text "Round" at -3141.24,3052.5 h60
  text "A" at -5931.59,3042.51 h66.67
  text "26" at -5396.62,2902.5 h60
  text "40.50mil (1.029mm)" at -4796.78,2902.5 h60
  text "PTH" at -3647.12,2902.5 h60
  text "Round" at -3141.24,2902.5 h60
  text "39" at -5396.62,2752.5 h60
  text "36.00mil (0.914mm)" at -4796.78,2752.5 h60
  text "PTH" at -3647.12,2752.5 h60
  text "Round" at -3141.24,2752.5 h60
  text "762" at -5396.62,2602.5 h60
  text "16.00mil (0.406mm)" at -4796.78,2602.5 h60
  text "PTH" at -3647.12,2602.5 h60
  text "Round" at -3141.24,2602.5 h60
  text "965 Total" at -5396.62,2452.5 h60

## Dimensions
3000,0 to 200,4800 on 7 Fab Notes
0,0 to 0,5500 on 7 Fab Notes
0,0 to 200,700 on 7 Fab Notes
0,0 to 4000,3000 on 7 Fab Notes
0,0 to 200,700 on 7 Fab Notes
0,0 to 4000,3000 on 7 Fab Notes
0,0 to 7800,700 on 7 Fab Notes
0,0 to 8000,0 on 7 Fab Notes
